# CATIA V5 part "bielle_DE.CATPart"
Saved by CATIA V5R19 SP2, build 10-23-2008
Part number: bielle_DE
Publications: "L_DE"
Bounding box of the stored display mesh (mm): x -260 to 260, y -10 to 10, z 0 to 10
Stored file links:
  D:\Dropbox\IAO_2011\MMS_GR2\IAO_2011_1521_alefevre\IAO_2011_1521_alefevre\bielle_DE.CATPart
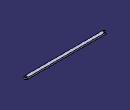
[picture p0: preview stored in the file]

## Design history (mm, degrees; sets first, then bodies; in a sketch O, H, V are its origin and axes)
Parameters
  L_DE = 500 mm
Body1 (main body)
  Sketch1 on xy-plane, origin (0, 0, 0), H (1, 0, 0), V (0, 1, 0)
    construction line L1 (-250, 0) -> (250, 0)
    point P1 (-250, 0)
    point P2 (250, 0)
    line L2 (-250, 10) -> (250, 10)
    line L3 (250, -10) -> (-250, -10)
    arc A1 centre (250, 0) radius 10 from (250, 10) to (250, -10) cw
    arc A2 centre (-250, 0) radius 10 from (-250, -10) to (-250, 10) cw
    circle A3 centre (250, 0) radius 5
    circle A4 centre (-250, 0) radius 5
    distance L1 L2 = 10
    radius A3 = 5
    radius A4 = 5
    distance P2 V = 250 {= L_DE /2}
    distance P1 P2 = 500 {= L_DE}
    coincidence: P1 H
    horizontal: L1 H
    tangency: A1 L2, A2 L2, A1 L3, A2 L3
  Pad1: profile Sketch1, direction (0, 0, 1), length 10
